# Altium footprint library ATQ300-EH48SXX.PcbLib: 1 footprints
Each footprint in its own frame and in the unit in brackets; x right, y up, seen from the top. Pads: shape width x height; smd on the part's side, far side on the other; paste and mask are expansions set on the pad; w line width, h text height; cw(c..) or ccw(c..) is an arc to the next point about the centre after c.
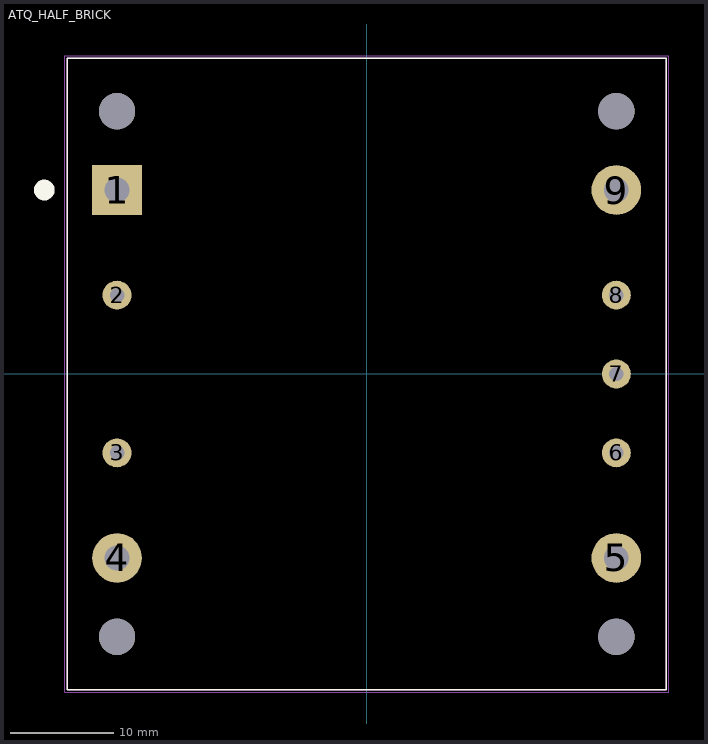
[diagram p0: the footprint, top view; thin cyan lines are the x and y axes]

## ATQ_HALF_BRICK [mm]
height 12.7
pads (13):
  rect 4.8x4.8 hole 2.4: 1(-24.125,17.78)
  round 2.8 hole 1.4: 2(-24.125,7.62) 3(-24.125,-7.62) 6(24.125,-7.62) 7(24.125,0) 8(24.125,7.62)
  round 4.8 hole 2.4: 4(-24.125,-17.78) 5(24.125,-17.78) 9(24.125,17.78)
  round 3.5 hole 3.5 unplated: ""(-24.125,-25.4) ""(-24.125,25.4) ""(24.125,-25.4) ""(24.125,25.4)
Top Overlay:
  circle w1: c-31.15,17.78 r0.5
  lines w0.127: -28.95,-30.5 28.95,-30.5 28.95,30.5 -28.95,30.5 -28.95,-30.5
Mechanical 13:
  circle w0.4: c-24.165,17.78 r0.2
  lines w0.127: -28.95,-30.5 28.95,-30.5 28.95,30.5 -28.95,30.5 -28.95,-30.5
Mechanical 15:
  lines w0.05: -29.2,-30.75 -29.2,30.75 29.2,30.75 29.2,-30.75 -29.2,-30.75
3D body "ATAQ_Half_Brick_ATQ300-EH48SXX.STEP": height 13.2, standoff -4.6, extent -28.95,-30.5 28.95,30.5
